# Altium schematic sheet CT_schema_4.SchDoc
size 430 x 328 mm
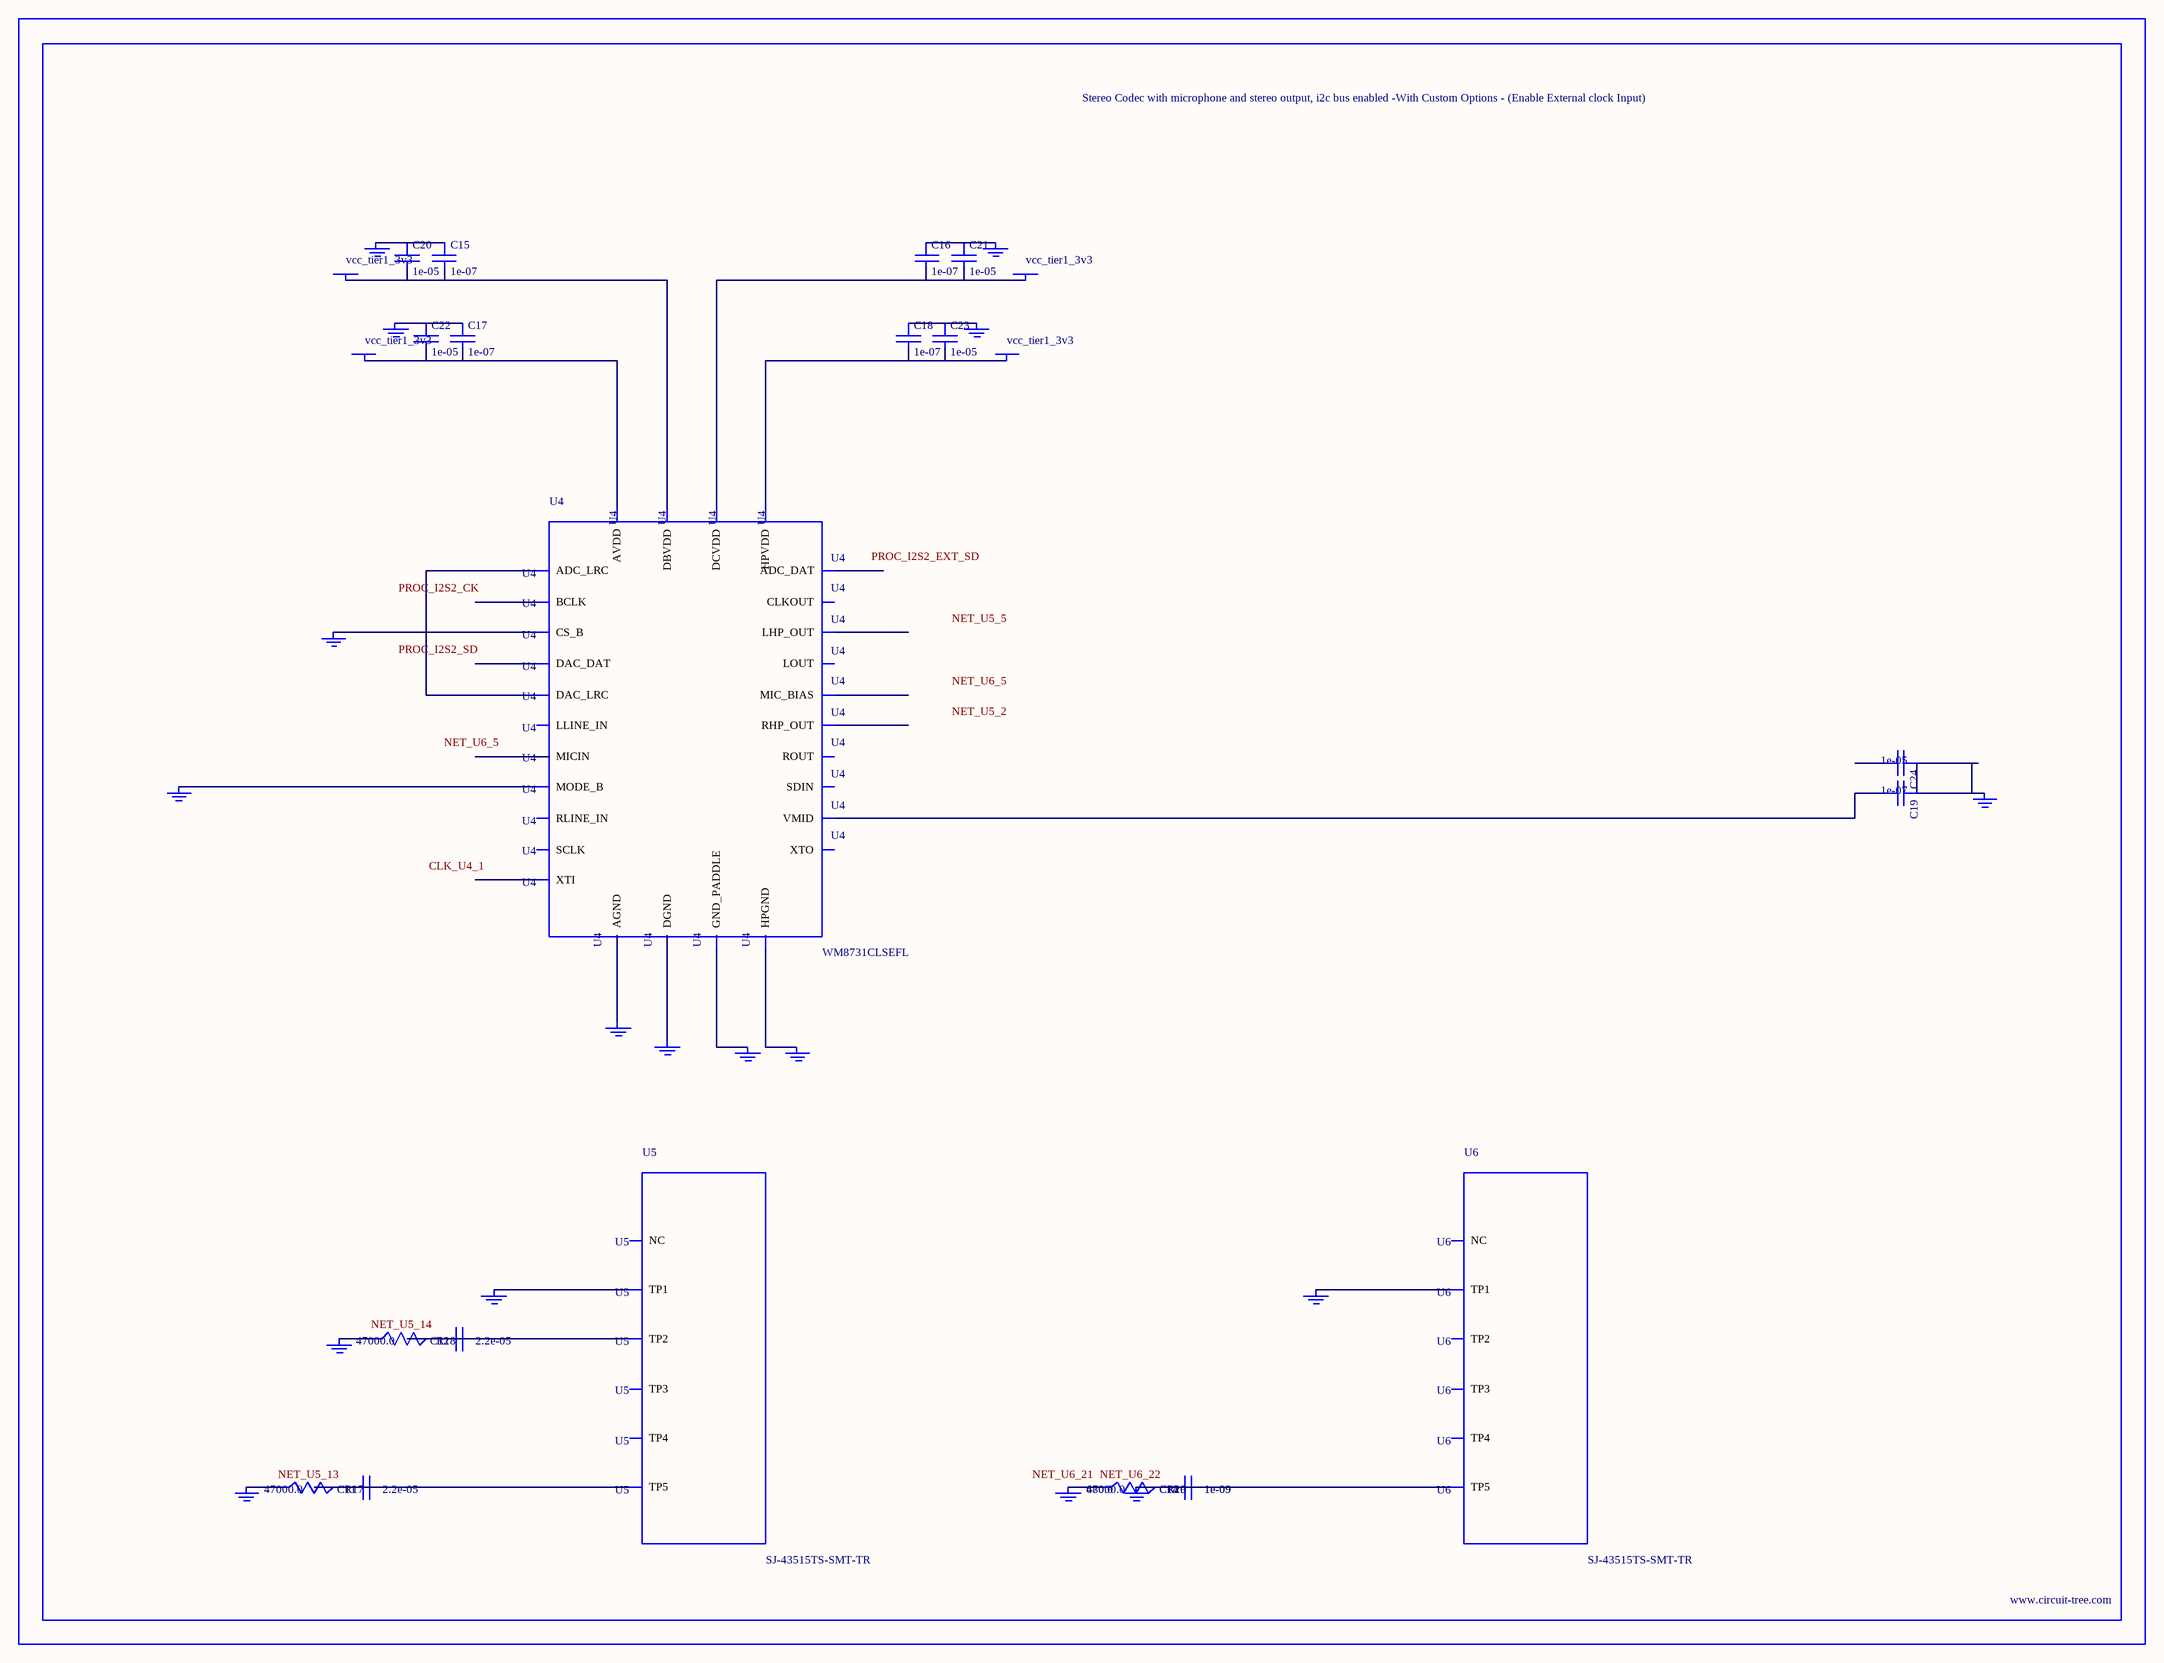
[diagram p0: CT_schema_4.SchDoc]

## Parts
BORDER3  (no value)
C11  2.2e-05  [C1210]
C12  2.2e-05  [C1210]
C13  1e-09  [C0402]
C14  1e-09  [C0402]
C15  1e-07  [C0402]
C16  1e-07  [C0402]
C17  1e-07  [C0402]
C18  1e-07  [C0402]
C19  1e-07  [C0402]
C20  1e-05  [C0805]
C21  1e-05  [C0805]
C22  1e-05  [C0805]
C23  1e-05  [C0805]
C24  1e-05  [C0805]
GND_INSTANCE_3_0  (no value)
GND_INSTANCE_3_1  (no value)
GND_INSTANCE_3_2  (no value)
GND_INSTANCE_3_3  (no value)
GND_INSTANCE_3_4  (no value)
GND_INSTANCE_3_5  (no value)
GND_INSTANCE_3_6  (no value)
GND_INSTANCE_3_7  (no value)
GND_INSTANCE_3_8  (no value)
GND_INSTANCE_3_9  (no value)
GND_INSTANCE_3_10  (no value)
GND_INSTANCE_3_11  (no value)
GND_INSTANCE_3_12  (no value)
GND_INSTANCE_3_13  (no value)
GND_INSTANCE_3_14  (no value)
GND_INSTANCE_3_15  (no value)
GND_INSTANCE_3_16  (no value)
POWER_INSTANCE_3_0  vcc_tier1_3v3
POWER_INSTANCE_3_1  vcc_tier1_3v3
POWER_INSTANCE_3_2  vcc_tier1_3v3
POWER_INSTANCE_3_3  vcc_tier1_3v3
R17  47000.0  [R0603]
R18  47000.0  [R0603]
R19  47000.0  [R0603]
R20  680.0  [R0603]
U4  WM8731CLSEFL  [QFN-28]
U5  SJ-43515TS-SMT-TR  [SJ-43515TS-SMT-TR]
U6  SJ-43515TS-SMT-TR  [SJ-43515TS-SMT-TR]

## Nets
NetC11_1: C11.1 C11.2 R17.2 U5.5(TP5)
NetC12_1: C12.1 C12.2 R18.2 U5.2(TP2)
NetC13_1: C13.1 C13.2 C14.1 C14.2 GND_INSTANCE_3_16.0(GND) R19.2 R20.2 U6.5(TP5)
NetC15_1: C15.1 C20.1 GND_INSTANCE_3_1.0(GND)
NetC15_2: C15.2 C20.2 POWER_INSTANCE_3_1.0(PWR) U4.5(DBVDD)
NetC16_1: C16.1 C21.1 GND_INSTANCE_3_0.0(GND)
NetC16_2: C16.2 C21.2 POWER_INSTANCE_3_0.0(PWR) U4.3(DCVDD)
NetC17_1: C17.1 C22.1 GND_INSTANCE_3_4.0(GND)
NetC17_2: C17.2 C22.2 POWER_INSTANCE_3_3.0(PWR) U4.18(AVDD)
NetC18_1: C18.1 C23.1 GND_INSTANCE_3_2.0(GND)
NetC18_2: C18.2 C23.2 POWER_INSTANCE_3_2.0(PWR) U4.12(HPVDD)
NetC19_1: C19.1 C24.1 GND_INSTANCE_3_5.0(GND)
NetC19_2: C19.2 U4.20(VMID)
NetGND_INSTANCE_3_3_0: GND_INSTANCE_3_3.0(GND) U4.15(HPGND)
NetGND_INSTANCE_3_6_0: GND_INSTANCE_3_6.0(GND) U4.25(MODE_B)
NetGND_INSTANCE_3_7_0: GND_INSTANCE_3_7.0(GND) U4.26(CS_B)
NetGND_INSTANCE_3_8_0: GND_INSTANCE_3_8.0(GND) U4.29(GND_PADDLE)
NetGND_INSTANCE_3_9_0: GND_INSTANCE_3_9.0(GND) U4.4(DGND)
NetGND_INSTANCE_3_10_0: GND_INSTANCE_3_10.0(GND) U4.19(AGND)
NetGND_INSTANCE_3_11_0: GND_INSTANCE_3_11.0(GND) U5.1(TP1)
NetGND_INSTANCE_3_12_0: GND_INSTANCE_3_12.0(GND) R18.1
NetGND_INSTANCE_3_13_0: GND_INSTANCE_3_13.0(GND) R17.1
NetGND_INSTANCE_3_14_0: GND_INSTANCE_3_14.0(GND) U6.1(TP1)
NetGND_INSTANCE_3_15_0: GND_INSTANCE_3_15.0(GND) R19.1 R20.1
NetU4_9: U4.9(DAC_LRC) U4.11(ADC_LRC)

Not connected (* = marked no-connect by the designer): C24 2; U4 1(XTI) 2(XTO) 6(CLKOUT) 7(BCLK) 8(DAC_DAT) 10(ADC_DAT) 13(LHP_OUT) 14(RHP_OUT) 16(LOUT) 17(ROUT) 21(MIC_BIAS) 22(MICIN) 23(RLINE_IN) 24(LLINE_IN) 27(SDIN) 28(SCLK); U5 3(TP3) 4(TP4) 6(NC); U6 2(TP2) 3(TP3) 4(TP4) 6(NC)

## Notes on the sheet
- Labels drawn without touching a wire or pin: CLK_U4_1, NET_U5_2, NET_U5_5, NET_U5_13, NET_U5_14, NET_U6_5, NET_U6_21, NET_U6_22, PROC_I2S2_CK, PROC_I2S2_EXT_SD, PROC_I2S2_SD

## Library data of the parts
BORDER3 = BORDER_PAGE3
C11 C12 = C1210C224K5RACTU
C13 C14 = C0402C102K3RAC
C15-C19 = C0402C104K3RACTU
C20-C24 = C0805C106K8RACTU
GND_INSTANCE_3_0-GND_INSTANCE_3_16 = GND
POWER_INSTANCE_3_0-POWER_INSTANCE_3_3 = PWR
R17-R19 = RC0603JR-0747KL
R20 = RC0603JR-07680RL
